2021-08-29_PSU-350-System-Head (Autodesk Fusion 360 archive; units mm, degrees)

design "PSU-350 System Head" references "MW-LRS-350", "486-1965-ND", "PSU-350 Vertical Desk", "PCB System Head 2021-08-26"
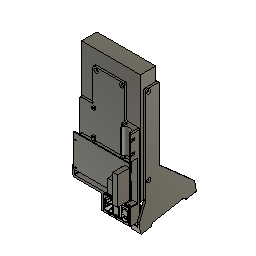
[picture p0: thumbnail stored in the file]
sketch "Sketch1" plane through (0, 0, 0) normal (0, 1, 0) x axis (1, 0, 0)
  line L1 (115, 0) -> (0, 0)
  line L2 (115, -215) -> (115, 0)
  line L3 (0, -215) -> (115, -215)
  line L4 (0, 0) -> (0, -215)
  line L5 (82.5, -32.5) -> (32.5, -32.5)
  line L6 (82.5, -182.5) -> (82.5, -32.5)
  line L7 (32.5, -182.5) -> (82.5, -182.5)
  line L8 (32.5, -32.5) -> (32.5, -182.5)
  line L9 (57.5, 0) -> (57.5, -32.5)
  line L10 (0, -107.5) -> (32.5, -107.5)
  line L11 (98.5, -14) -> (7.5, -14)
  line L12 (98.5, -61) -> (98.5, -14)
  line L13 (7.5, -61) -> (98.5, -61)
  line L14 (7.5, -14) -> (7.5, -61)
  line L15 (113.5, -10) -> (3.5, -10)
  line L16 (113.5, -73) -> (113.5, -10)
  line L17 (3.5, -73) -> (113.5, -73)
  line L18 (3.5, -10) -> (3.5, -73)
  line L19 (63.1, 5) -> (110, 5)
  line L20 (63.1, 29.4) -> (63.1, 5)
  line L21 (110, 29.4) -> (63.1, 29.4)
  line L22 (110, 5) -> (110, 29.4)
  line L23 (112, 3) -> (61.1, 3)
  line L24 (112, 31.4) -> (112, 3)
  line L25 (61.1, 31.4) -> (112, 31.4)
  line L26 (61.1, 3) -> (61.1, 31.4)
  line L27 (114, -75) -> (114, 34.4)
  line L28 (26.5, -188.5) -> (88.5, -188.5)
  line L29 (1, 5) -> (1, -124)
  line L30 (56.1, 5) -> (1, 5)
  line L31 (56.1, 34.4) -> (56.1, 5)
  line L32 (114, 34.4) -> (56.1, 34.4)
  line L33 (1, 0.5) -> (114, 0.5)
  line L34 (90.5, -66) -> (3.5, -66)
  line L35 (90.5, -122) -> (90.5, -66)
  line L36 (3.5, -122) -> (90.5, -122)
  line L37 (3.5, -66) -> (3.5, -122)
  line L38 (87, -118.5) -> (29, -118.5)
  line L39 (87, -69.5) -> (87, -118.5)
  line L40 (29, -69.5) -> (87, -69.5)
  line L41 (29, -118.5) -> (29, -69.5)
  line L42 (26.5, -124) -> (1, -124)
  line L43 (26.5, -188.5) -> (26.5, -124)
  line L44 (88.5, -124) -> (88.5, -188.5)
  line L45 (92.5, -124) -> (88.5, -124)
  line L46 (92.5, -75) -> (92.5, -124)
  line L47 (114, -75) -> (92.5, -75)
  line L48 (89.75, -64.35) -> (101.85, -64.35)
  line L49 (89.75, -72.25) -> (89.75, -64.35)
  line L50 (84.25, -72.25) -> (89.75, -72.25)
  line L51 (84.25, -61.8) -> (84.25, -72.25)
  line L52 (95.15, -61.8) -> (84.25, -61.8)
  line L53 (95.15, -57.65) -> (95.15, -61.8)
  line L54 (101.85, -57.65) -> (95.15, -57.65)
  line L55 (101.85, -64.35) -> (101.85, -57.65)
  line L56 (4.15, -57.65) -> (4.15, -64.35)
  line L57 (10.85, -57.65) -> (4.15, -57.65)
  line L58 (10.85, -61.8) -> (10.85, -57.65)
  line L59 (31.75, -61.8) -> (10.85, -61.8)
  line L60 (31.75, -72.25) -> (31.75, -61.8)
  line L61 (26.25, -72.25) -> (31.75, -72.25)
  line L62 (26.25, -64.35) -> (26.25, -72.25)
  line L63 (4.15, -64.35) -> (26.25, -64.35)
  line L64 (95.15, -64.35) -> (95.15, -61.8)
  line L65 (10.85, -64.35) -> (10.85, -61.8)
  line L66 (31.75, -121.25) -> (26.25, -121.25)
  line L67 (31.75, -115.75) -> (31.75, -121.25)
  line L68 (26.25, -115.75) -> (31.75, -115.75)
  line L69 (26.25, -121.25) -> (26.25, -115.75)
  line L70 (89.75, -121.25) -> (84.25, -121.25)
  line L71 (89.75, -115.75) -> (89.75, -121.25)
  line L72 (84.25, -115.75) -> (89.75, -115.75)
  line L73 (84.25, -121.25) -> (84.25, -115.75)
  line L74 (10.85, -17.35) -> (1, -17.35)
  line L75 (10.85, -10.65) -> (10.85, -17.35)
  line L76 (1, -10.65) -> (10.85, -10.65)
  line L77 (95.15, 0.5) -> (95.15, -17.35)
  line L78 (101.85, -17.35) -> (95.15, -17.35)
  line L79 (101.85, 0.5) -> (101.85, -17.35)
  line L80 (84.25, -61.8) -> (31.75, -61.8)
  line L81 (31.75, -64.35) -> (84.25, -64.35)
  line L82 (31.75, -64.35) -> (26.25, -64.35)
  line L83 (89.75, -64.35) -> (84.25, -64.35)
  line L84 (95.15, -10.65) -> (10.85, -10.65)
  line L85 (10.85, -13.2) -> (95.15, -13.2)
  line L86 (4.15, -17.35) -> (4.15, -57.65)
  line L87 (6.7, -17.35) -> (6.7, -57.65)
  line L88 (3.55, 0.5) -> (3.55, -10.65)
  line L89 (111, -76) -> (93, -76)
  line L90 (111, -115.5104) -> (111, -76)
  line L91 (93, -115.5104) -> (111, -115.5104)
  line L92 (93, -76) -> (93, -115.5104)
  line L93 (114, -124) -> (92.5, -124)
  line L94 (114, -75) -> (114, -124)
  circle C1 centre (32.5, -182.5) radius 2.125
  circle C2 centre (82.5, -182.5) radius 2.125
  circle C3 centre (32.5, -32.5) radius 2.125
  circle C4 centre (82.5, -32.5) radius 2.125
  circle C5 centre (82.5, -32.5) radius 4
  circle C6 centre (7.5, -14) radius 1.35
  circle C7 centre (7.5, -61) radius 1.35
  circle C8 centre (98.5, -61) radius 1.35
  circle C9 centre (98.5, -14) radius 1.35
  circle C10 centre (7.5, -14) radius 3
  circle C11 centre (29, -118.5) radius 1
  circle C12 centre (29, -69.5) radius 1
  circle C13 centre (87, -69.5) radius 1
  circle C14 centre (87, -118.5) radius 1
  circle C15 centre (98.5, -61) radius 3.35
  circle C16 centre (87, -69.5) radius 2.75
  circle C17 centre (29, -69.5) radius 2.75
  circle C18 centre (7.5, -61) radius 3.35
  circle C19 centre (29, -118.5) radius 2.75
  circle C20 centre (87, -118.5) radius 2.75
  circle C21 centre (98.5, -14) radius 3.35
  circle C22 centre (7.5, -14) radius 3.35
  point P1 (0, 0)
  point P2 (0, 0)
  point P15 (57.5, -32.5)
  point P16 (57.5, 0)
  point P17 (32.5, -107.5)
  point P18 (0, -107.5)
  point P9 (32.5, -182.5)
  point P10 (32.5, -182.5)
  point P8 (82.5, -182.5)
  point P11 (82.5, -182.5)
  point P6 (32.5, -32.5)
  point P12 (32.5, -32.5)
  point P7 (82.5, -32.5)
  point P14 (82.5, -32.5)
  point P19 (7.5, -14)
  point P23 (7.5, -14)
  point P22 (7.5, -61)
  point P24 (7.5, -61)
  point P21 (98.5, -61)
  point P25 (98.5, -61)
  point P20 (98.5, -14)
  point P26 (98.5, -14)
  point P40 (114, 34.4)
  point P44 (114, 34.4)
  point P45 (114, 0.5)
  point P46 (1, 0.5)
  point P31 (3.5, -73)
  point P51 (29, -118.5)
  point P55 (29, -118.5)
  point P54 (29, -69.5)
  point P56 (29, -69.5)
  point P53 (87, -69.5)
  point P57 (87, -69.5)
  point P52 (87, -118.5)
  point P58 (87, -118.5)
  point P60 (26.5, -124)
  point P67 (101.85, -64.35)
  point P75 (101.85, -64.35)
  point P80 (29, -118.5)
  point P81 (87, -118.5)
  point P27 (7.5, -14)
  point P83 (7.5, -14)
  point P82 (98.5, -14)
  point P84 (4.15, -64.35)
  point P92 (4.15, -64.35)
  point P93 (95.15, -64.35)
  point P94 (10.85, -64.35)
  point P103 (1, -17.35)
  point P106 (1, -10.65)
  point P108 (95.15, 0.5)
  point P110 (101.85, 0.5)
  point P68 (89.75, -64.35)
  point P111 (84.25, -64.35)
  point P112 (31.75, -64.35)
  point P91 (26.25, -64.35)
  point P113 (95.15, -10.65)
  point P114 (95.15, -13.2)
  point P115 (10.85, -13.2)
  point P116 (4.15, -17.35)
  point P117 (6.7, -57.65)
  point P118 (6.7, -17.35)
  point P119 (3.55, -10.65)
  point P120 (3.55, 0.5)
  point P125 (102, -76)
  point P66 (114, -75)
  point P127 (114, -75)
  point P3 (115, 0)
  point P5 (0, -215)
  point P28 (3.5, -10)
  point P29 (113.5, -10)
  point P34 (63.1, 29.4)
  point P35 (110, 29.4)
  point P33 (63.1, 5)
  point P38 (112, 31.4)
  point P49 (90.5, -122)
  point P50 (3.5, -122)
  point P47 (3.5, -66)
  point P105 (10.85, -10.65)
  point P123 (111, -115.5104)
  point P124 (93, -115.5104)
  point P30 (113.5, -73)
  horizontal L1
  vertical L2
  horizontal L3
  vertical L4
  coincident P1 P2
  horizontal L5
  vertical L6
  horizontal L7
  vertical L8
  equal C2 C3
  equal C3 C4
  equal C1 C4
  concentric C4 C5
  midpoint L5 P15
  midpoint L1 P16
  vertical L9
  midpoint L8 P17
  midpoint L4 P18
  horizontal L10
  coincident P9 P10
  coincident P8 P11
  coincident P6 P12
  coincident P7 P14
  horizontal L11
  vertical L12
  horizontal L13
  vertical L14
  equal C8 C9
  equal C6 C9
  equal C6 C7
  concentric C6 C10
  horizontal L15
  vertical L16
  horizontal L17
  vertical L18
  coincident P19 P23
  coincident P22 P24
  coincident P21 P25
  coincident P20 P26
  horizontal L19
  vertical L20
  horizontal L21
  vertical L22
  horizontal L23
  vertical L24
  horizontal L25
  vertical L26
  perpendicular L17 L27
  perpendicular L18 L28
  perpendicular L1 L29
  perpendicular L18 L30
  perpendicular L30 L31
  perpendicular L31 L32
  coincident P40 P44
  coincident L27 P45
  coincident L29 P46
  perpendicular L29 L33
  horizontal L34
  vertical L35
  horizontal L36
  vertical L37
  coincident P31 L37
  horizontal L38
  vertical L39
  horizontal L40
  vertical L41
  coincident P51 P55
  coincident P54 P56
  coincident P53 P57
  coincident P52 P58
  equal C11 C12
  equal C13 C14
  equal C11 C14
  perpendicular L29 L42
  perpendicular L28 L43
  perpendicular L28 L44
  perpendicular L44 L45
  perpendicular L28 L46
  perpendicular L27 L47
  coincident P60 L45
  horizontal L48
  perpendicular L48 L49
  perpendicular L39 L50
  perpendicular L13 L51
  perpendicular L51 L52
  perpendicular L13 L53
  perpendicular L12 L54
  perpendicular L54 L55
  coincident P67 P75
  concentric C8 C15
  concentric C13 C16
  tangent L50 C16
  tangent L49 C16
  tangent L51 C16
  tangent L48 C15
  tangent L55 C15
  tangent L54 C15
  tangent L53 C15
  concentric C12 C17
  concentric C7 C18
  equal C19 C20
  equal C17 C20
  equal C16 C17
  coincident P55 P80
  coincident P58 P81
  equal C21 C22
  equal C18 C21
  equal C15 C18
  coincident P27 P83
  coincident P26 P82
  perpendicular L34 L56
  perpendicular L56 L57
  perpendicular L13 L58
  perpendicular L58 L59
  perpendicular L40 L60
  perpendicular L58 L61
  perpendicular L34 L62
  perpendicular L62 L63
  coincident P84 P92
  tangent C18 L56
  tangent C18 L57
  tangent C18 L58
  tangent C17 L62
  tangent C17 L61
  tangent C17 L60
  coincident L48 P93
  perpendicular L48 L64
  coincident L63 P94
  perpendicular L63 L65
  horizontal L66
  vertical L67
  horizontal L68
  vertical L69
  horizontal L70
  vertical L71
  horizontal L72
  vertical L73
  tangent C20 L70
  tangent C20 L71
  tangent C20 L72
  tangent C20 L73
  tangent C19 L67
  tangent C19 L66
  tangent C19 L69
  tangent C19 L68
  coincident L29 P103
  perpendicular L29 L74
  perpendicular L11 L75
  coincident L29 P106
  perpendicular L29 L76
  coincident L33 P108
  perpendicular L1 L77
  perpendicular L12 L78
  coincident L33 P110
  perpendicular L33 L79
  tangent C21 L78
  tangent C21 L79
  tangent C21 L77
  tangent C22 L76
  tangent C22 L75
  tangent C22 L74
  coincident P68 L63
  coincident L51 P111
  coincident L60 P112
  perpendicular L60 L81
  coincident P91 L81
  coincident L77 P113
  perpendicular L77 L84
  coincident L77 P114
  perpendicular L77 L85
  coincident L75 P115
  coincident L74 P116
  perpendicular L74 L86
  coincident L57 P117
  coincident L74 P118
  perpendicular L74 L87
  coincident L76 P119
  coincident L33 P120
  perpendicular L33 L88
  horizontal L89
  vertical L90
  horizontal L91
  vertical L92
  midpoint L89 P125
  perpendicular L46 L93
  perpendicular L93 L94
  coincident P66 P127
  dimension "d1" diameter C4 = 4.25
  dimension "d2" diameter C5 = 8
  dimension "d3" distance P2 P3 = 115
  dimension "d4" distance P2 P5 = 215
  dimension "d5" distance P6 P9 = 150
  dimension "d6" distance P6 P7 = 50
  dimension "d7" diameter C6 = 2.7
  dimension "d8" diameter C10 = 6
  dimension "d9" distance P19 P20 = 91
  dimension "d10" distance P19 P22 = 47 (= "51 mm - 4 mm")
  dimension "d11" distance P19 L18 = 4
  dimension "d12" distance P19 P28 = 4
  dimension "d13" distance P28 P31 = 63
  dimension "d14" distance P28 P29 = 110
  dimension "d15" distance L2 L16 = 1.5
  dimension "d16" distance P3 L15 = 10
  dimension "d17" distance P34 P35 = 46.9
  dimension "d18" distance P33 P34 = 24.4
  dimension "d19" distance P35 L25 = 2
  dimension "d20" distance L22 L24 = 2 (= "d19")
  dimension "d21" distance L20 L26 = 2 (= "d19")
  dimension "d22" distance L19 L23 = 2 (= "d19")
  dimension "d23" distance P3 L23 = 3
  dimension "d24" distance P3 L24 = 3
  dimension "d26" distance P3 L27 = 1
  dimension "d27" distance P38 L32 = 3
  dimension "d28" distance L26 L31 = 5
  dimension "d29" distance L1 L30 = 5
  dimension "d30" distance P3 L33 = 0.5
  dimension "d31" distance P1 L29 = 1
  dimension "d32" distance P40 L28 = 222.9
  dimension "d33" distance P49 P50 = 87
  dimension "d34" distance P51 P54 = 49
  dimension "d35" distance L36 L38 = 3.5
  dimension "d36" distance P24 L40 = 8.5
  dimension "d38" distance P47 P54 = 3.5
  dimension "d39" distance P31 L41 = 25.5
  dimension "d40" distance P31 L39 = 83.5
  dimension "d41" diameter C11 = 2
  dimension "d42" distance P10 L28 = 6
  dimension "d43" distance P10 L43 = 6 (= "d42")
  dimension "d44" distance P11 L44 = 6 (= "d42")
  dimension "d45" distance P50 L42 = 2
  dimension "d46" distance P49 L46 = 2
  dimension "d47" distance L17 L47 = 2
  dimension "d48" distance C8 C15 = 2
  dimension "d49" diameter C16 = 5.5
  dimension "d50" distance P68 L52 = 2.55
  dimension "d51" distance L59 L63 = 2.55
  dimension "d60" distance P105 L85 = 2.55
  dimension "d61" distance P116 L87 = 2.55
  dimension "d66" distance P46 L88 = 2.55
  dimension "d88" distance P123 P124 = 18
  dimension "d89" distance P30 P125 = 11.5
  dimension "d90" distance P66 L89 = 1
extrude "Extrude1" new body sketch "Sketch1" profile of C1 C2 C3 C4 C6 C7 C8 C9 L23 L24 L25 L26 L27 L28 L29 L30 L31 L32 L33 C11 C12 C13 C14 L42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 against normal blind 4
extrude "Extrude2" sketch "Sketch1" profile of C11 C12 C13 C14 L48 L49 L50 L51 L52 L59 L60 L61 L62 L63 L64 L65 L66 L67 L68 L69 L70 L71 L72 L73 blind -2.5
extrude "Extrude3" add sketch "Sketch1" profile of C6 C7 C8 C9 L29 L33 L48 L53 L54 L55 L56 L57 L58 L63 L64 L65 L74 L75 L76 L77 L78 L79 to an object offset 11
extrude "Extrude4" add sketch "Sketch1" profile of L48 L51 L52 L57 L59 L60 L63 L64 L65 L74 L75 L77 L80 L81 L82 L83 L84 L85 L86 L87 to an object offset -3
extrude "Extrude5" add sketch "Sketch1" profile of L23 L24 L25 L26 L27 L29 L30 L31 L32 L33 L76 L88 to an object
extrude "Extrude6" sketch "Sketch1" profile of L19 L20 L21 L22 L23 L24 L25 L26 blind 3
extrude "Extrude7" add sketch "Sketch1" profile of L46 L47 L93 L94 to an object
sketch "Sketch2" plane through (0, 0, 124) normal (0, 0, 1) x axis (-1, 0, 0)
  line L1 (-88.5, 0) -> (-114, 0)
  line L2 (-88.5, 4) -> (-88.5, 0)
  line L3 (-92.5, 4) -> (-88.5, 4)
  line L4 (-92.5, 17.5) -> (-92.5, 4)
  line L5 (-114, 17.5) -> (-92.5, 17.5)
  line L6 (-114, 0) -> (-114, 17.5)
  line L7 (-102, 0) -> (-102, 17.5)
  circle C1 centre (-102, 17.5) radius 9
  arc A1 centre (-102, 17.5) radius 11 clockwise from (-92.5, 11.9547) to (-113, 17.5)
  arc A2 centre (-102, 17.5) radius 12.5 clockwise from (-92.5, 9.376) to (-114, 14)
  point P8 (-102, 17.5)
  point P10 (-102, 17.5)
  point P9 (-102, 0)
  point P11 (-102, 0)
  point P14 (-92.5, 11.9547)
  point P12 (-102, 17.5)
  point P17 (-92.5, 9.376)
  point P15 (-102, 17.5)
  point P16 (-114, 14)
  point P13 (-113, 17.5)
  coincident L5 P8
  coincident P8 P10
  coincident P9 P11
  vertical L7
  coincident L4 P14
  coincident P8 P12
  coincident L4 P17
  coincident P12 P15
  coincident L6 P16
  coincident L5 P13
  dimension "d93" diameter C1 = 18
  dimension "d96" distance C1 A1 = 2
  dimension "d97" distance A1 A2 = 1.5
extrude "Extrude8" cut sketch "Sketch2" profile of L5 C1 to an object
extrude "Extrude9" cut sketch "Sketch2" profile of L4 L5 L6 A1 A2 blind -5 from offset -10
extrude "Extrude10" sketch "Sketch2" profile of L4 L5 L6 A1 A2 blind 5 from offset 10
fillet "Fillet4" radius 1
chamfer "Chamfer1" distance 2 distance 2
chamfer "Chamfer2" distance 2
fillet "Fillet1" radius 0.75
fillet "Fillet2" radius 2
chamfer "Chamfer3" distance 13.5
fillet "Fillet3" radius 1
offset_faces "OffsetFaces1" distance -2
component_insert "Component Insert1"
joint "Assemble1" alignAngle 0 alignOffsetX 0 alignOffsetY 0 alignOffsetZ 0
component_insert "Component Insert2"
joint "Assemble2" alignAngle 0 alignOffsetX 0 alignOffsetY 0 alignOffsetZ 0
component_insert "Component Insert3"
joint "Assemble3" alignAngle 90 alignOffsetX 0 alignOffsetY 0 alignOffsetZ 0
component_insert "Component Insert4"
joint "Assemble4" alignAngle 90 alignOffsetX 0 alignOffsetY 0 alignOffsetZ 0
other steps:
joint_origin "JointOrigin1"
joint_origin "JointOrigin2"
joint_origin "JointOrigin3"

design "PCB System Head 2021-08-26"
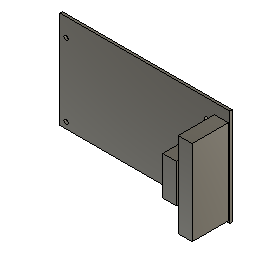
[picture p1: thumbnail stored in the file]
sketch "Sketch1" plane through (0, 0, 0) normal (0, 1, 0) x axis (1, 0, 0)
  line L1 (110, 0) -> (0, 0)
  line L2 (110, -63) -> (110, 0)
  line L3 (0, -63) -> (110, -63)
  line L4 (0, 0) -> (0, -63)
  line L5 (95, -4) -> (4, -4)
  line L6 (95, -51) -> (95, -4)
  line L7 (4, -51) -> (95, -51)
  line L8 (4, -4) -> (4, -51)
  line L9 (109, -1) -> (100, -1)
  line L10 (109, -56) -> (109, -1)
  line L11 (100, -56) -> (109, -56)
  line L12 (100, -1) -> (100, -56)
  line L13 (90, -16) -> (99, -16)
  line L14 (90, -41) -> (90, -16)
  line L15 (99, -41) -> (90, -41)
  line L16 (99, -16) -> (99, -41)
  line L17 (100, -28.5) -> (99, -28.5)
  circle C1 centre (4, -4) radius 1.35
  circle C2 centre (4, -51) radius 1.35
  circle C3 centre (95, -51) radius 1.35
  circle C4 centre (95, -4) radius 1.35
  circle C5 centre (95, -4) radius 3
  point P1 (0, 0)
  point P2 (0, 0)
  point P6 (4, -4)
  point P7 (4, -4)
  point P10 (4, -51)
  point P11 (4, -51)
  point P9 (95, -51)
  point P12 (95, -51)
  point P8 (95, -4)
  point P13 (95, -4)
  point P23 (99, -28.5)
  point P24 (100, -28.5)
  point P3 (110, 0)
  point P5 (0, -63)
  point P16 (109, -56)
  point P17 (100, -56)
  point P15 (109, -1)
  point P20 (90, -16)
  point P21 (90, -41)
  horizontal L1
  vertical L2
  horizontal L3
  vertical L4
  coincident P1 P2
  horizontal L5
  vertical L6
  horizontal L7
  vertical L8
  coincident P6 P7
  coincident P10 P11
  coincident P9 P12
  coincident P8 P13
  equal C1 C2
  equal C1 C3
  equal C1 C4
  horizontal L9
  vertical L10
  horizontal L11
  vertical L12
  concentric C4 C5
  horizontal L13
  vertical L14
  horizontal L15
  vertical L16
  equal L11 L15
  midpoint L16 P23
  midpoint L12 P24
  horizontal L17
  dimension "d1" distance P2 P3 = 110
  dimension "d2" distance P2 P5 = 63
  dimension "d3" diameter C1 = 2.7
  dimension "d5" distance P1 P6 = 4
  dimension "d6" distance P1 P6 = 4
  dimension "d7" distance P1 P11 = 51
  dimension "d8" distance P1 P13 = 95
  dimension "d9" distance P16 P17 = 9
  dimension "d10" distance P15 P16 = 55
  dimension "d11" distance P3 L9 = 1
  dimension "d12" diameter C5 = 6
  dimension "d13" distance L2 L10 = 1
  dimension "d14" distance P23 P24 = 1
  dimension "d15" distance P20 P21 = 25
extrude "Extrude1" new body sketch "Sketch1" profile of L1 L2 L3 L4 C1 C2 C3 C4 L9 L10 L11 L12 L13 L14 L15 L16 against normal blind 1.6
extrude "Extrude2" add sketch "Sketch1" profile of L9 L10 L11 L12 L13 L14 L15 L16 against normal blind 25

design "MW-LRS-350"
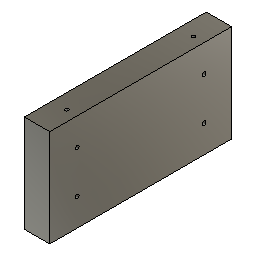
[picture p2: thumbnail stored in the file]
sketch "Sketch1" plane through (0, 0, 0) normal (0, 1, 0) x axis (1, 0, 0)
  line L1 (-33.16, -7.3872) -> (-5.66, -7.3872)
  line L2 (-33.16, -69.3872) -> (-33.16, -7.3872)
  line L3 (-5.66, -69.3872) -> (-33.16, -69.3872)
  line L4 (-5.66, -7.3872) -> (-5.66, -69.3872)
  line L5 (30, 0) -> (0, 0)
  line L6 (30, -115) -> (30, 0)
  line L7 (0, -115) -> (30, -115)
  line L8 (0, 0) -> (0, -115)
  line L9 (-34.61, -0.1) -> (-4.21, -0.1)
  line L10 (-34.61, -76.6744) -> (-34.61, -0.1)
  line L11 (-4.21, -76.6744) -> (-34.61, -76.6744)
  line L12 (-4.21, -0.1) -> (-4.21, -76.6744)
  line L13 (-4.21, -0.1) -> (-34.61, -76.6744)
  line L14 (-5.66, -69.3872) -> (-33.16, -7.3872)
  line L15 (-43.61, 0) -> (0, 0)
  line L16 (-43.61, -76.7744) -> (-43.61, 0)
  line L17 (-4.11, -76.7744) -> (-43.61, -76.7744)
  line L18 (-4.11, -115) -> (-4.11, -76.7744)
  line L19 (0, -115) -> (-4.11, -115)
  line L20 (-34.71, 0) -> (-34.71, -76.7744)
  line L21 (-27.41, -2.9315) -> (-27.41, -7.3872)
  line L22 (-11.41, -2.9315) -> (-27.41, -2.9315)
  line L23 (-11.41, -7.3872) -> (-11.41, -2.9315)
  line L24 (-27.41, -73.8428) -> (-27.41, -69.3872)
  line L25 (-11.41, -73.8428) -> (-27.41, -73.8428)
  line L26 (-11.41, -69.3872) -> (-11.41, -73.8428)
  line L27 (-4.11, 0) -> (-4.11, -76.7744)
  line L28 (42, -6) -> (30, -6)
  line L29 (42, 6) -> (42, -6)
  line L30 (-43.61, 6) -> (42, 6)
  line L31 (-43.61, 0) -> (-43.61, 6)
  line L32 (-5.66, -7.3872) -> (8, -112)
  line L33 (8, -3) -> (8, -112)
  line L34 (30, -3) -> (8, -3)
  point P1 (0, 0)
  point P14 (-19.41, -38.3872)
  point P15 (-19.41, -38.3872)
  point P16 (0, 0)
  point P21 (0, -115)
  point P9 (0, -115)
  point P22 (-34.71, -76.7744)
  point P23 (-34.71, 0)
  point P24 (-27.41, -7.3872)
  point P27 (-11.41, -7.3872)
  point P28 (-27.41, -69.3872)
  point P31 (-11.41, -69.3872)
  point P32 (-4.11, 0)
  point P33 (30, -6)
  point P17 (-43.61, 0)
  point P37 (-43.61, 0)
  point P38 (30, -112)
  point P41 (30, -3)
  point P6 (0, 0)
  point P7 (30, 0)
  point P8 (30, -115)
  point P4 (-33.16, -69.3872)
  point P5 (-5.66, -69.3872)
  point P3 (-33.16, -7.3872)
  point P11 (-34.61, -0.1)
  point P12 (-34.61, -76.6744)
  point P13 (-4.21, -76.6744)
  point P25 (-27.41, -2.9315)
  point P19 (-4.11, -76.7744)
  point P34 (42, -6)
  point P35 (42, 6)
  horizontal L1
  vertical L2
  horizontal L3
  vertical L4
  horizontal L5
  vertical L6
  horizontal L7
  vertical L8
  coincident P1 L8
  coincident P1 L5
  horizontal L9
  vertical L10
  horizontal L11
  vertical L12
  midpoint L13 P14
  midpoint L14 P15
  coincident P14 P15
  coincident P1 P16
  perpendicular L8 L15
  perpendicular L15 L16
  perpendicular L16 L17
  perpendicular L17 L18
  coincident L8 P21
  perpendicular L8 L19
  coincident P9 P21
  coincident L17 P22
  perpendicular L17 L20
  coincident L15 P23
  coincident L1 P24
  perpendicular L1 L21
  perpendicular L21 L22
  coincident L1 P27
  perpendicular L1 L23
  coincident L3 P28
  perpendicular L3 L24
  perpendicular L24 L25
  coincident L3 P31
  perpendicular L3 L26
  coincident P24 L24
  coincident P27 L26
  equal L21 L24
  perpendicular L15 L27
  coincident L15 P32
  coincident L6 P33
  perpendicular L6 L28
  perpendicular L5 L29
  perpendicular L16 L30
  perpendicular L30 L31
  coincident P17 P37
  coincident L6 P38
  perpendicular L6 L32
  perpendicular L32 L33
  coincident L6 P41
  perpendicular L6 L34
  dimension "d1" distance P6 P7 = 30
  dimension "d2" distance P7 P8 = 115
  dimension "d3" distance P4 P5 = 27.5
  dimension "d4" distance P3 P4 = 62
  dimension "d6" distance P11 P12 = 76.5744
  dimension "d7" distance P12 P13 = 30.4
  dimension "d9" distance P1 L9 = 0.1
  dimension "d10" distance P9 L18 = 4.11
  dimension "d11" distance L11 L17 = 0.1
  dimension "d12" distance L10 L16 = 9
  dimension "d13" distance L10 L20 = 0.1
  dimension "d15" distance P24 P25 = 4.4557
  dimension "d16" distance P14 L24 = 8
  dimension "d17" distance P15 L26 = 8 (= "d16")
  dimension "d18" distance L12 P19 = 0.1
  dimension "d42" distance P33 P34 = 12
  dimension "d43" distance L5 L30 = 6
  dimension "d44" distance P34 P35 = 12
  dimension "d214" distance P7 L34 = 3
  dimension "d215" = 3 (= "d214")
  dimension "d216" distance L8 L33 = 8
  dimension "d29" Radius = 3
  dimension "d30" Radius = 1
  dimension "d31" Radius = 1
  dimension "d40" diameter = 4.25
  dimension "d41" distance = 12.5
  dimension "d45" AlongDistance = 25
  dimension "d46" TaperAngle = 0
  dimension "d47" Radius = 1
  dimension "d48" diameter = 6
  dimension "d49" diameter = 15
  dimension "d50" distance = 6
  dimension "d52" distance = 2.54
  dimension "d53" distance = 2.54 (= "d52")
  dimension "d55" distance = 2.54
  dimension "d56" distance = 6
  dimension "d57" AlongDistance = -12
  dimension "d58" TaperAngle = 0
  dimension "d60" diameter = 4.25
  dimension "d61" distance = 0.1
  dimension "d67" Side1Offset = 0
  dimension "d68" TaperAngle = 0
  dimension "d69" AlongDistance = -12
  dimension "d70" TaperAngle = 0
  dimension "d71" AlongDistance = -45
  dimension "d72" TaperAngle = 0
  dimension "d73" AlongDistance = 25
  dimension "d74" TaperAngle = 0
  dimension "d75" distance = 20
  dimension "d76" distance = 20
  dimension "d77" distance = 20
  dimension "d78" distance = 20
  dimension "d79" distance = 15
  dimension "d80" distance = 25
  dimension "d81" distance = 15
  dimension "d82" diameter = 5.4
  dimension "d83" distance = 6.5
  dimension "d84" distance = 6.5
  dimension "d85" distance = 8
  dimension "d86" distance = 6.5
  dimension "d87" distance = 3
  dimension "d88" Side1Offset = 0
  dimension "d89" TaperAngle = 0
  dimension "d90" distance = -0.1
  dimension "d91" distance = -0.1
  dimension "d92" Radius = 1
  dimension "d95" Radius = 2
  dimension "d96" Radius = 1
  dimension "d97" Radius = 2
  dimension "d98" Radius = 2
  dimension "d99" Radius = 2
  dimension "d100" Radius = 2
  dimension "d101" distance = 5
  dimension "d102" distance = 1
  dimension "d103" distance = 1
  dimension "d104" distance = 5
  dimension "d105" AlongDistance = 4
  dimension "d106" TaperAngle = 0
  dimension "d107" AlongDistance = -3
  dimension "d108" TaperAngle = 0
  dimension "d109" leftDistance = 2
  dimension "d110" Radius = 2
  dimension "d111" Radius = 1
  dimension "d112" distance = 1.97
  dimension "d113" distance = 1
  dimension "d114" distance = 1.7
  dimension "d115" distance = 4.4
  dimension "d116" distance = 4.4
  dimension "d117" distance = 4.4 (= "d116")
  dimension "d118" distance = 4.4 (= "d116")
  dimension "d119" distance = 4.4 (= "d116")
  dimension "d120" distance = 4.4 (= "d116")
  dimension "d121" distance = 4.4 (= "d116")
  dimension "d122" distance = 4.4 (= "d116")
  dimension "d123" distance = 4.4 (= "d116")
  dimension "d124" distance = 4.4 (= "d116")
  dimension "d125" Radius = 2
  dimension "d126" distance = 3.25
  dimension "d127" distance = 2.54
  dimension "d128" distance = 2.54 (= "d127")
  dimension "d129" distance = 2.54 (= "d127")
  dimension "d130" distance = 9
  dimension "d131" AlongDistance = -10
  dimension "d132" TaperAngle = 0
  dimension "d133" Radius = 4
  dimension "d134" Radius = 1.5
  dimension "d135" rightDistance = 4
  dimension "d136" distance = 12
  dimension "d137" distance = 0.25
  dimension "d140" Side1Offset = 0.1
  dimension "d141" TaperAngle = 0
  dimension "d145" distance = 55
  dimension "d146" distance = 24
  dimension "d147" diameter = 2.9
  dimension "d148" distance = 5
  dimension "d149" distance = 45
  dimension "d150" distance = 1
  dimension "d151" distance = 15
  dimension "d152" distance = 6
  dimension "d153" distance = 3.37
  dimension "d154" distance = 3.37
  dimension "d155" Side1Offset = 0
  dimension "d156" TaperAngle = 0
  dimension "d157" distance = 0.5
  dimension "d158" ProfileOffset = 0
  dimension "d159" Side1Offset = 0
  dimension "d160" TaperAngle = 0
  dimension "d161" ProfileOffset = 0
  dimension "d162" Side1Offset = 0
  dimension "d163" TaperAngle = 0
  dimension "d164" distance = 6
  dimension "d165" Radius = 3
  dimension "d166" Radius = 1
  dimension "d167" Radius = 1
  dimension "d168" distance = 30
  dimension "d169" distance = 34
  dimension "d176" distance = 22
  dimension "d177" distance = 14
  dimension "d178" distance = 2
  dimension "d179" distance = 2
  dimension "d180" diameter = 2.9
  dimension "d181" distance = 11
  dimension "d182" distance = 1
  dimension "d185" distance = 30
  dimension "d186" distance = 34
  dimension "d187" distance = 22
  dimension "d188" distance = 14
  dimension "d189" distance = 2
  dimension "d190" distance = 2
  dimension "d191" diameter = 2.9
  dimension "d192" distance = 11
  dimension "d193" distance = 1
  dimension "d194" distance = 10
  dimension "d195" distance = 1
  dimension "d196" distance = 1
  dimension "d197" distance = 70
  dimension "d198" distance = 63
  dimension "d199" distance = 28
  dimension "d200" distance = 71
  dimension "d202" distance = 14
  dimension "d203" diameter = 2.9
  dimension "d204" distance = 1
  dimension "d205" distance = 1
  dimension "d206" distance = 40
  dimension "d207" Side1Offset = 0
  dimension "d208" TaperAngle = 0
  dimension "d209" ProfileOffset = 0
  dimension "d210" Side1Offset = 0
  dimension "d211" TaperAngle = 0
  dimension "d212" Side1Offset = 0
  dimension "d213" TaperAngle = 0
extrude "Extrude5" new body sketch "Sketch1" profile of L5 L6 L7 L8 L32 L33 L34 along normal blind 215 Linear Dimension-10 3.37 Linear Dimension-11 3.37
sketch "Sketch2" plane through (0, 0, 0) normal (-1, 0, 0) x axis (0, -1, 0)
  line L1 (0, 115) -> (0, 0)
  line L2 (-215, 115) -> (0, 115)
  line L3 (-215, 0) -> (-215, 115)
  line L4 (0, 0) -> (-215, 0)
  line L5 (-182.5, 32.5) -> (-32.5, 32.5)
  line L6 (-182.5, 82.5) -> (-182.5, 32.5)
  line L7 (-32.5, 82.5) -> (-182.5, 82.5)
  line L8 (-32.5, 32.5) -> (-32.5, 82.5)
  line L9 (-32.5, 32.5) -> (-182.5, 82.5)
  line L10 (-107.5, 0) -> (-107.5, 115)
  line L11 (-200, 113) -> (-215, 113)
  line L12 (-200, 2) -> (-200, 113)
  line L13 (-215, 2) -> (-200, 2)
  curve K1
  circle C1 centre (-182.5, 82.5) radius 2.25
  circle C2 centre (-182.5, 32.5) radius 2.25
  circle C3 centre (-32.5, 32.5) radius 2.25
  circle C4 centre (-32.5, 82.5) radius 2.25
  circle C5 centre (-47.45, 78.3) radius 26
  point P11 (-107.5, 57.5)
  point P10 (-107.5, 57.5)
  point P8 (-182.5, 82.5)
  point P12 (-182.5, 82.5)
  point P7 (-182.5, 32.5)
  point P13 (-182.5, 32.5)
  point P6 (-32.5, 32.5)
  point P14 (-32.5, 32.5)
  point P9 (-32.5, 82.5)
  point P15 (-32.5, 82.5)
  point P16 (-107.5, 115)
  point P17 (-107.5, 0)
  point P19 (-215, 113)
  point P22 (-215, 2)
  point P18 (-47.45, 78.3)
  point P21 (-200, 2)
  horizontal L5
  vertical L6
  horizontal L7
  vertical L8
  midpoint L9 P11
  coincident P10 P11
  coincident P8 P12
  coincident P7 P13
  coincident P6 P14
  coincident P9 P15
  equal C3 C4
  equal C2 C4
  equal C1 C2
  coincident L2 P16
  coincident L4 P17
  perpendicular L4 L10
  midpoint P10 L10
  coincident L3 P19
  perpendicular L3 L11
  perpendicular L11 L12
  perpendicular L12 L13
  coincident L3 P22
  dimension "d34" distance P6 P9 = 50
  dimension "d35" distance P8 P9 = 150
  dimension "d36" diameter C4 = 4.5
  dimension "d220" distance L2 P18 = 36.7
  dimension "d221" distance L1 P18 = 47.45
  dimension "d222" diameter C5 = 52
  dimension "d223" distance L2 L11 = 2
  dimension "d224" distance L4 L13 = 2
  dimension "d225" distance P21 P22 = 15
  dimension "d238" distance L3 P13 = 32.5
extrude "Extrude6" sketch "Sketch2" profile of C1 C2 C3 C4 blind 4
extrude "Extrude26" cut sketch "Sketch2" profile of L3 L11 L12 L13 to an object offset 5
extrude "Extrude27" cut sketch "Sketch2" profile of C4 C5 against normal blind 1
sketch "Sketch10" plane through (0, 0, 115) normal (0, 0, 1) x axis (-1, 0, 0)
  line L1 (-30, 0) -> (0, 0)
  line L2 (-30, -215) -> (-30, 0)
  line L3 (0, -215) -> (-30, -215)
  line L4 (0, 0) -> (0, -215)
  line L5 (-17.5, -32.5) -> (-17.5, -182.5)
  line L6 (-17.5, -32.5) -> (0, -32.5)
  line L7 (-17.5, -182.5) -> (0, -182.5)
  circle C1 centre (-17.5, -32.5) radius 2
  circle C2 centre (-17.5, -182.5) radius 2
  point P7 (-17.5, -182.5)
  point P8 (-17.5, -182.5)
  point P6 (-17.5, -32.5)
  point P9 (-17.5, -32.5)
  point P10 (0, -32.5)
  point P12 (0, -32.5)
  point P11 (0, -182.5)
  point P14 (0, -182.5)
  point P15 (-17.5, -182.5)
  point P13 (-17.5, -32.5)
  coincident P7 P8
  vertical L5
  coincident P6 P9
  equal C1 C2
  coincident P10 P12
  perpendicular L4 L6
  coincident P11 P14
  perpendicular L4 L7
  coincident P7 P15
  coincident P6 P13
  dimension "d231" diameter C2 = 4
  dimension "d232" distance L2 L5 = 12.5
extrude "Extrude28" cut sketch "Sketch10" profile of C1 C2 against normal blind 5
extrude "Extrude29" sketch "Sketch10" profile of C1 C2 blind 5
named bodies: "PSU"

design "486-1965-ND"
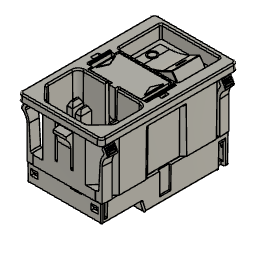
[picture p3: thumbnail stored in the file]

design "PSU-350 Vertical Desk"
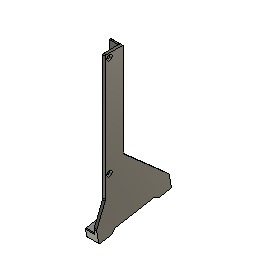
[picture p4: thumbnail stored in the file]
sketch "Sketch1" plane through (0, 0, 0) normal (1, 0, 0) x axis (0, 1, 0)
  line L1 (0, 150) -> (0, 0)
  line L2 (17.5, -32.5) -> (-12.5, -32.5)
  line L3 (91.8082, -59.9687) -> (-16.5206, -79.07)
  line L4 (-15.6524, -83.9941) -> (-16.5206, -79.07)
  line L5 (4.0438, -80.5211) -> (-15.6524, -83.9941)
  line L6 (8.0996, -74.7288) -> (4.0438, -80.5211)
  line L7 (92.6765, -64.8928) -> (91.8082, -59.9687)
  line L8 (72.9803, -68.3657) -> (92.6765, -64.8928)
  line L9 (67.188, -64.3099) -> (72.9803, -68.3657)
  line L10 (89.2035, -45.1966) -> (91.8082, -59.9687)
  line L11 (21.05, 15) -> (89.2035, -45.1966)
  line L12 (-6, 156) -> (21.05, 156)
  line L13 (-6, -31.5) -> (-6, 156)
  line L14 (-19.1253, -64.2979) -> (-6, -31.5)
  line L15 (-16.5206, -79.07) -> (-19.1253, -64.2979)
  line L16 (6.7104, -66.8504) -> (8.0996, -74.7288)
  line L17 (-17.9098, -71.1916) -> (6.7104, -66.8504)
  line L18 (65.7989, -56.4315) -> (67.188, -64.3099)
  line L19 (90.419, -52.0903) -> (65.7989, -56.4315)
  line L20 (18.5, -34.5) -> (18.5, 156)
  line L21 (21.05, -13.5048) -> (69.0098, -55.8653)
  line L22 (21.05, 156) -> (21.05, -13.5048)
  line L23 (21.05, -16.907) -> (65.7989, -56.4315)
  line L24 (1.9682, -75.8099) -> (18.5, -34.5)
  line L25 (21.05, -34.9913) -> (21.05, -16.907)
  line L26 (4.9234, -75.2889) -> (21.05, -34.9913)
  circle C1 centre (0, 150) radius 2.125
  circle C2 centre (0, 0) radius 2.125
  circle C3 centre (0, 0) radius 4
  point P1 (0, 0)
  point P2 (0, 0)
  point P3 (0, 150)
  point P4 (0, 150)
  point P5 (0, 0)
  point P13 (8.0996, -74.7288)
  point P16 (67.188, -64.3099)
  point P15 (72.9803, -68.3657)
  point P23 (-17.9098, -71.1916)
  point P25 (90.419, -52.0903)
  point P24 (65.7989, -56.4315)
  point P26 (18.5, 156)
  point P28 (69.0098, -55.8653)
  point P30 (21.05, 156)
  point P32 (1.9682, -75.8099)
  point P18 (21.05, 15)
  point P34 (4.9234, -75.2889)
  point P29 (21.05, -13.5048)
  point P6 (0, 0)
  point P7 (-12.5, -32.5)
  point P8 (17.5, -32.5)
  point P9 (-16.5206, -79.07)
  point P10 (91.8082, -59.9687)
  point P11 (-15.6524, -83.9941)
  point P12 (4.0438, -80.5211)
  point P21 (-19.1253, -64.2979)
  point P20 (-6, -31.5)
  point P27 (18.5, -34.5)
  coincident P1 P2
  vertical L1
  coincident P3 P4
  coincident P1 P5
  equal C1 C2
  concentric C2 C3
  horizontal L2
  perpendicular L3 L4
  perpendicular L4 L5
  coincident L3 P13
  perpendicular L3 L7
  perpendicular L7 L8
  coincident L3 P16
  coincident L5 P15
  equal L5 L8
  perpendicular L3 L10
  perpendicular L2 L13
  parallel L4 L15
  equal L10 L15
  parallel L15 L16
  coincident L15 P23
  perpendicular L15 L17
  perpendicular L3 L18
  coincident L10 P25
  perpendicular L10 L19
  coincident L17 P24
  coincident L12 P26
  perpendicular L2 L20
  coincident L19 P28
  coincident L12 P30
  perpendicular L12 L22
  parallel L11 L21
  parallel L21 L23
  coincident L3 P32
  parallel L14 L24
  coincident P18 L22
  vertical L25
  coincident L3 P34
  coincident P29 L25
  parallel L24 L26
  dimension "d1" distance P2 P3 = 150
  dimension "d2" diameter C2 = 4.25
  dimension "d3" diameter C3 = 8
  dimension "d4" distance P6 L2 = 32.5
  dimension "d5" distance P6 P7 = 12.5
  dimension "d6" distance P7 P8 = 30
  dimension "d7" angle L1 L3 = 80
  dimension "d8" distance P9 P10 = 110
  dimension "d9" angle L5 L6 = 45
  dimension "d10" angle L8 L9 = 45
  dimension "d11" distance P11 P12 = 20
  dimension "d12" distance P4 L13 = 6
  dimension "d14" distance P4 L12 = 6
  dimension "d16" distance P9 P21 = 15
  dimension "d17" distance P9 P11 = 5
  dimension "d18" distance L2 P20 = 1
  dimension "d19" distance P6 P18 = 15
  dimension "d20" distance P6 L3 = 75
  dimension "d21" distance P6 L15 = 30
  dimension "d22" distance P21 L17 = 7
  dimension "d24" distance L20 L22 = 2.55
  dimension "d26" distance L21 L23 = 2.55
  dimension "d36" distance P8 L20 = 1
  dimension "d37" distance L2 P27 = 2
  dimension "d39" distance L24 L26 = 2.55 (= "d26")
extrude "Extrude1" new body sketch "Sketch1" profile of C1 C2 L3 L4 L5 L6 L7 L8 L9 L10 L11 L12 L13 L14 L15 L16 L17 L18 L19 L20 L21 L22 L23 L24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 along normal blind 4
extrude "Extrude2" add sketch "Sketch1" profile of L3 L4 L5 L6 L7 L8 L9 L10 L12 L15 L16 L17 L18 L19 L20 L21 L22 L23 L24 L25 L26 against normal blind 14
sketch "Sketch2" plane through (0, 13.8919, -78.7846) normal (0, 0.1736, -0.9848) x axis (-1, 0, 0)
  line L1 (-4, 80) -> (14, 80)
  line L2 (-4, 60) -> (-4, 80)
  line L3 (14, 60) -> (-4, 60)
  line L4 (14, 80) -> (14, 60)
  line L5 (-4, -10) -> (14, -10)
  line L6 (-4, -30) -> (-4, -10)
  line L7 (14, -30) -> (-4, -30)
  line L8 (14, -10) -> (14, -30)
  line L9 (5, -30) -> (5, 80)
  circle C1 centre (5, 71) radius 7
  circle C2 centre (5, -21) radius 7
  circle C3 centre (5, 71) radius 1.5
  circle C4 centre (5, -21) radius 1.5
  point P12 (5, 80)
  point P13 (5, -30)
  point P11 (5, -21)
  point P6 (5, 71)
  equal C1 C2
  midpoint L1 P12
  midpoint L7 P13
  coincident P11 L9
  coincident P6 L9
  concentric C1 C3
  concentric C2 C4
  equal C3 C4
  dimension "d40" diameter C1 = 14
  dimension "d41" distance L1 P6 = 9
  dimension "d42" distance L7 P11 = 9 (= "d41")
  dimension "d43" diameter C3 = 3
extrude "Extrude3" cut sketch "Sketch2" profile of C3 C4 to an object
extrude "Extrude4" cut sketch "Sketch2" profile of C1 C2 C3 C4 against normal blind 5
chamfer "Chamfer1" distance 2
fillet "Fillet3" ChordLen 2
fillet "Fillet4" ChordLen 1.5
